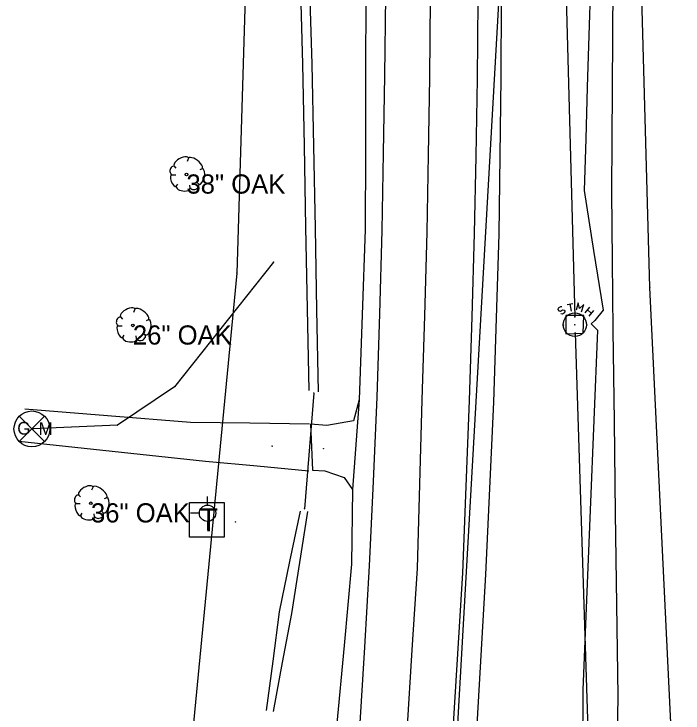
# Model space of a CAD drawing. Extents: x 1930288 to 1941089, y 588389 to 611475.
# Drawn here: x 1930813.6 to 1930987.9, y 598727.5 to 598909.6 of the extents above; entities that cross this region are included whole.
import ezdxf

# ---------------------------------------------------------------- set-up
doc = ezdxf.new("R2010")
doc.units = 0
for name, color, linetype in [('S_BASELINE', 7, 'Continuous'), ('S_DITCHLINE', 7, 'Continuous'), ('S_DRG_PT_SYM', 7, 'Continuous'), ('S_DRIVEWAY', 7, 'Continuous'), ('S_DROP_INLET', 7, 'Continuous'), ('S_EDGE_PAVEMENT', 7, 'Continuous'), ('S_GAS_UTILITIES', 7, 'Continuous'), ('S_MSC_PT_SYM', 7, 'Continuous'), ('S_PAVEMENT_CROWN', 7, 'Continuous'), ('S_SANITARY_SEWER', 7, 'Continuous'), ('S_SHOULDER', 7, 'Continuous'), ('S_SIDE_DRAIN', 7, 'Continuous'), ('S_STORM_SEWER', 7, 'Continuous'), ('S_TELEPHONE_UTILITIES', 7, 'Continuous'), ('S_TREE', 7, 'Continuous'), ('S_TREE_ANNOT', 7, 'Continuous'), ('S_UTILITY_POLE', 7, 'Continuous'), ('S_UTL_PT_SYM', 7, 'Continuous'), ('S_WATER_UTILITIES', 7, 'Continuous')]:
    doc.layers.add(name, color=color, linetype=linetype)

msp = doc.modelspace()

# ---------------------------------------------------------------- linework, layer by layer
at = {"layer": 'S_BASELINE'}
msp.add_line((1930894.27, 598110.49), (1930946.09, 599020.44), dxfattribs=at)
at = {"layer": 'S_DITCHLINE'}
for points in [[(1930885.69, 599030.55), (1930886.05, 599007.92), (1930886.41, 598985.29), (1930886.99, 598963.11), (1930887.58, 598940.93), (1930888.17, 598918.74), (1930888.75, 598896.56), (1930889.17, 598875.3), (1930889.58, 598854.04), (1930889.99, 598832.79), (1930890.41, 598811.53)], [(1930887.77, 599030.24), (1930888.22, 599008.14), (1930888.67, 598986.05), (1930889.3, 598963.68), (1930889.92, 598941.3), (1930890.55, 598918.93), (1930891.18, 598896.56), (1930891.61, 598875.21), (1930892.04, 598853.86), (1930892.46, 598832.51), (1930892.89, 598811.16)], [(1930958.74, 599016.33), (1930965.42, 599014.25), (1930966.89, 599005.44), (1930968.46, 598988.34), (1930970.03, 598971.25), (1930969.93, 598957.75), (1930969.84, 598944.26), (1930969.75, 598930.76), (1930969.66, 598917.27), (1930969.57, 598903.78), (1930969.47, 598890.28), (1930969.38, 598876.79), (1930969.29, 598863.29), (1930969.48, 598845.28), (1930969.68, 598827.26), (1930969.99, 598803.42), (1930970.29, 598779.58), (1930970.6, 598755.74), (1930970.91, 598731.9), (1930970.72, 598716.01)], [(1930958.59, 599014.73), (1930963.59, 599004.53), (1930964.52, 598987.9), (1930965.44, 598971.28), (1930965.04, 598957.82), (1930964.63, 598944.36), (1930964.22, 598930.9), (1930963.81, 598917.44), (1930963.41, 598903.98), (1930963, 598890.52), (1930962.59, 598877.06), (1930962.18, 598863.6), (1930964.65, 598848.03), (1930967.12, 598832.47), (1930964.95, 598829.79), (1930963.99, 598828.88), (1930965.68, 598827.27), (1930964.71, 598803.83), (1930963.74, 598780.39), (1930962.77, 598756.95), (1930961.8, 598733.51), (1930961.71, 598717.5)], [(1930888.13, 598780.09), (1930885.41, 598767), (1930882.7, 598753.91), (1930881.02, 598741.02), (1930879.34, 598728.13)], [(1930890.05, 598779.98), (1930887.96, 598766.7), (1930885.88, 598753.42), (1930883.52, 598740.66), (1930881.15, 598727.9)]]:
    msp.add_lwpolyline(points, dxfattribs=at)
at = {"layer": 'S_DRG_PT_SYM'}
for points in [[(1930891.72, 598810.87), (1930891.72, 598810.92), (1930891.72, 598810.87), (1930891.67, 598810.87), (1930891.72, 598810.87), (1930891.72, 598810.82), (1930891.72, 598810.87), (1930891.77, 598810.87)], [(1930889.32, 598780.73), (1930889.32, 598780.78), (1930889.32, 598780.73), (1930889.27, 598780.73), (1930889.32, 598780.73), (1930889.32, 598780.68), (1930889.32, 598780.73), (1930889.37, 598780.73)]]:
    msp.add_lwpolyline(points, dxfattribs=at)
at = {"layer": 'S_DRIVEWAY'}
for points in [[(1930903.51, 598809.06), (1930902.06, 598803.64), (1930895.14, 598802.42), (1930890.87, 598802.72), (1930891.4, 598790.75), (1930894.6, 598790.63), (1930899.62, 598788.9), (1930901.82, 598785.75)], [(1930890.56, 598802.74), (1930875.07, 598802.99), (1930859.57, 598803.23), (1930837.99, 598804.94), (1930816.4, 598806.66)], [(1930814.83, 598798.29), (1930839.15, 598795.7), (1930863.46, 598793.11), (1930876.95, 598791.87), (1930890.44, 598790.62)]]:
    msp.add_lwpolyline(points, dxfattribs=at)
at = {"layer": 'S_DROP_INLET'}
for points in [[(1930957.38, 598831.05), (1930957.37, 598826.27), (1930961.93, 598826.44), (1930962.11, 598831.03)], [(1930962.11, 598831.03), (1930957.38, 598831.05)]]:
    msp.add_lwpolyline(points, dxfattribs=at)
at = {"layer": 'S_EDGE_PAVEMENT'}
for points in [[(1930908.24, 599094.62), (1930908.7, 599076.29), (1930909.15, 599057.96), (1930909.61, 599039.62), (1930910.07, 599021.29), (1930910.34, 598999.36), (1930910.62, 598977.42), (1930910.62, 598956.27), (1930910.61, 598935.13), (1930910.4, 598914.36), (1930910.19, 598893.6), (1930909.84, 598873.38), (1930909.49, 598853.17), (1930908.82, 598831.47), (1930908.16, 598809.77), (1930907.16, 598787.82), (1930906.16, 598765.87), (1930904.92, 598744.7), (1930903.67, 598723.53)], [(1930932.32, 599092.44), (1930932.75, 599074.74), (1930933.17, 599057.04), (1930933.6, 599039.34), (1930934.02, 599021.64), (1930934.34, 598999.38), (1930934.66, 598977.12), (1930934.67, 598955.54), (1930934.68, 598933.95), (1930934.5, 598913.33), (1930934.31, 598892.71), (1930933.93, 598872.55), (1930933.55, 598852.4), (1930932.9, 598830.68), (1930932.25, 598808.95), (1930931.34, 598786.48), (1930930.43, 598764), (1930929.16, 598742.91), (1930927.89, 598721.82)]]:
    msp.add_lwpolyline(points, dxfattribs=at)
at = {"layer": 'S_GAS_UTILITIES'}
for p, q in [((1930881.2, 598844.97), (1930855.39, 598812.45)), ((1930855.39, 598812.45), (1930840.55, 598802.53)), ((1930814.96, 598798.2), (1930821.58, 598804.82)), ((1930814.96, 598804.82), (1930821.58, 598798.2)), ((1930840.55, 598802.53), (1930818.55, 598801.52))]:
    msp.add_line(p, q, dxfattribs=at)
msp.add_circle((1930818.27, 598801.51), 4.68, dxfattribs=at)
at = {"layer": 'S_MSC_PT_SYM'}
for points in [[(1930959.75, 598830.72), (1930959.75, 598830.77), (1930959.75, 598830.72), (1930959.7, 598830.72), (1930959.75, 598830.72), (1930959.75, 598830.67), (1930959.75, 598830.72), (1930959.8, 598830.72)], [(1930956.8, 598828.6), (1930956.8, 598828.65), (1930956.8, 598828.6), (1930956.75, 598828.6), (1930956.8, 598828.6), (1930956.8, 598828.55), (1930956.8, 598828.6), (1930956.85, 598828.6)], [(1930962.91, 598828.62), (1930962.91, 598828.67), (1930962.91, 598828.62), (1930962.86, 598828.62), (1930962.91, 598828.62), (1930962.91, 598828.57), (1930962.91, 598828.62), (1930962.96, 598828.62)], [(1930959.85, 598826.59), (1930959.85, 598826.64), (1930959.85, 598826.59), (1930959.8, 598826.59), (1930959.85, 598826.59), (1930959.85, 598826.54), (1930959.85, 598826.59), (1930959.9, 598826.59)], [(1930880.87, 598797.04), (1930880.87, 598797.09), (1930880.87, 598797.04), (1930880.82, 598797.04), (1930880.87, 598797.04), (1930880.87, 598796.99), (1930880.87, 598797.04), (1930880.92, 598797.04)], [(1930894.28, 598796.41), (1930894.28, 598796.46), (1930894.28, 598796.41), (1930894.23, 598796.41), (1930894.28, 598796.41), (1930894.28, 598796.35), (1930894.28, 598796.41), (1930894.33, 598796.41)]]:
    msp.add_lwpolyline(points, dxfattribs=at)
at = {"layer": 'S_PAVEMENT_CROWN'}
msp.add_lwpolyline([(1930919.68, 599093.9), (1930920.14, 599075.83), (1930920.59, 599057.77), (1930921.04, 599039.71), (1930921.49, 599021.64), (1930921.81, 598999.22), (1930922.13, 598976.81), (1930922.17, 598955.6), (1930922.2, 598934.39), (1930922.05, 598913.69), (1930921.9, 598892.99), (1930921.54, 598872.9), (1930921.18, 598852.8), (1930920.54, 598830.95), (1930919.9, 598809.1), (1930919.28, 598787.14), (1930918.67, 598765.18), (1930917.3, 598743.97), (1930915.93, 598722.77)], dxfattribs=at)
at = {"layer": 'S_SANITARY_SEWER'}
for p, q in [((1930979.26, 598838.38), (1930967.81, 599265.02)), ((1930987.94, 598658.53), (1930979.26, 598838.38))]:
    msp.add_line(p, q, dxfattribs=at)
at = {"layer": 'S_SHOULDER'}
for points in [[(1930937.38, 599115.75), (1930938.49, 599091.15), (1930939.12, 599068.01), (1930939.38, 599055.8), (1930939.72, 599039.21), (1930940.06, 599022.62), (1930940.02, 598999.95), (1930939.99, 598977.27), (1930940.29, 598955.61), (1930940.58, 598933.95), (1930940.54, 598913.5), (1930940.49, 598893.05), (1930940.2, 598872.63), (1930939.9, 598852.22), (1930939.23, 598830.34), (1930938.55, 598808.45), (1930937.5, 598786.02), (1930936.44, 598763.59), (1930935.25, 598742.5), (1930934.05, 598721.41)], [(1930901.66, 599094.84), (1930902.24, 599076.43), (1930902.81, 599058.02), (1930903.38, 599039.62), (1930903.95, 599021.21), (1930904.32, 598999.45), (1930904.69, 598977.7), (1930904.98, 598956.64), (1930905.27, 598935.59), (1930905.24, 598914.82), (1930905.22, 598894.05), (1930905.16, 598873.77), (1930905.09, 598853.48), (1930904.3, 598831.27), (1930903.51, 598809.06), (1930901.82, 598785.75), (1930901.57, 598766.31), (1930899.62, 598745.09), (1930897.67, 598723.87)]]:
    msp.add_lwpolyline(points, dxfattribs=at)
at = {"layer": 'S_SIDE_DRAIN'}
msp.add_line((1930891.72, 598810.87), (1930889.32, 598780.73), dxfattribs=at)
at = {"layer": 'S_STORM_SEWER'}
for p, q in [((1930954.8, 599013.58), (1930959.75, 598830.72)), ((1930955.97, 598833.36), (1930955.42, 598832.98)), ((1930956.39, 598833.29), (1930955.97, 598833.36)), ((1930957.71, 598833.95), (1930959.22, 598834.22)), ((1930958.48, 598834.1), (1930958.83, 598832.16)), ((1930962.4, 598831.74), (1930963.64, 598833.21)), ((1930955.42, 598832.98), (1930955.35, 598832.59)), ((1930955.35, 598832.59), (1930955.54, 598832.32)), ((1930955.54, 598832.32), (1930955.97, 598832.2)), ((1930955.97, 598832.2), (1930956.51, 598832.55)), ((1930956.51, 598831.39), (1930956.12, 598831.47)), ((1930956.51, 598832.55), (1930956.97, 598832.47)), ((1930957.05, 598831.78), (1930956.51, 598831.39)), ((1930956.97, 598832.47), (1930957.13, 598832.2)), ((1930957.13, 598832.2), (1930957.05, 598831.78)), ((1930963.06, 598832.51), (1930964.03, 598831.7)), ((1930964.61, 598832.4), (1930963.37, 598830.92)), ((1930959.85, 598826.59), (1930965.03, 598662.59))]:
    msp.add_line(p, q, dxfattribs=at)
msp.add_lwpolyline([(1930961.51, 598832.05), (1930962.05, 598833.91), (1930961, 598832.9), (1930960.62, 598834.33), (1930960.07, 598832.47)], dxfattribs=at)
msp.add_circle((1930959.75, 598828.67), 3.05, dxfattribs=at)
at = {"layer": 'S_TELEPHONE_UTILITIES'}
msp.add_lwpolyline([(1930859.33, 598773.36), (1930859.33, 598782.36), (1930868.33, 598782.36), (1930868.33, 598773.36)], close=True, dxfattribs=at)
at = {"layer": 'S_TREE'}
for p, q in [((1930859.08, 598872.07), (1930858.7, 598871.22)), ((1930855.29, 598870.06), (1930855.79, 598869.47)), ((1930854.63, 598867.73), (1930855.75, 598867.73)), ((1930862.65, 598869.28), (1930861.99, 598869.01)), ((1930855.79, 598864.55), (1930856.26, 598865.25)), ((1930859.47, 598864.28), (1930859.39, 598865.06)), ((1930861.87, 598865.17), (1930861.41, 598865.6)), ((1930845.12, 598832.74), (1930844.74, 598831.89)), ((1930841.33, 598830.73), (1930841.83, 598830.14)), ((1930848.69, 598829.95), (1930848.03, 598829.68)), ((1930840.67, 598828.4), (1930841.79, 598828.4)), ((1930841.83, 598825.22), (1930842.29, 598825.92)), ((1930847.91, 598825.84), (1930847.45, 598826.27)), ((1930845.51, 598824.95), (1930845.43, 598825.73)), ((1930834.2, 598786.39), (1930833.81, 598785.54)), ((1930830.4, 598784.38), (1930830.91, 598783.8)), ((1930837.77, 598783.6), (1930837.11, 598783.33)), ((1930829.74, 598782.05), (1930830.87, 598782.05)), ((1930830.91, 598778.88), (1930831.37, 598779.57)), ((1930834.59, 598778.6), (1930834.51, 598779.38)), ((1930836.99, 598779.5), (1930836.53, 598779.92))]:
    msp.add_line(p, q, dxfattribs=at)
for centre in [(1930858.53, 598867.82), (1930844.57, 598828.49), (1930833.64, 598782.15)]:
    msp.add_circle(centre, 0.341, dxfattribs=at)
for centre, major_axis, ratio, start_param, end_param in [((1930857.19, 598871.03), (1.86, 1.08), 0.471018, 0, 3.141593), ((1930860.85, 598870.7), (-1.81, 1.36), 0.405113, 3.141593, 6.283186), ((1930854.96, 598868.91), (0.31, 1.03), 0.646762, 0, 3.141593), ((1930855.26, 598866.26), (-0.61, 1.6), 0.420543, 6.283185, 9.424777), ((1930862.2, 598867.29), (0.46, 2.04), 0.482994, 3.141593, 6.283185), ((1930857.72, 598864.48), (-1.83, 0.19), 0.529943, 0, 3.141593), ((1930860.68, 598864.77), (1.09, 0.46), 0.711534, 3.141592, 6.283185), ((1930843.23, 598831.7), (1.86, 1.08), 0.471018, 0, 3.141593), ((1930846.88, 598831.37), (-1.81, 1.36), 0.405113, 3.141593, 6.283186), ((1930840.99, 598829.58), (0.31, 1.03), 0.646762, 0, 3.141593), ((1930848.24, 598827.96), (0.46, 2.04), 0.482994, 3.141593, 6.283185), ((1930841.3, 598826.93), (-0.61, 1.6), 0.420543, 6.283185, 9.424777), ((1930846.72, 598825.44), (1.09, 0.46), 0.711534, 3.141592, 6.283185), ((1930843.76, 598825.15), (-1.83, 0.19), 0.529943, 0, 3.141593), ((1930832.31, 598785.35), (1.86, 1.08), 0.471018, 0, 3.141593), ((1930835.96, 598785.03), (-1.81, 1.36), 0.405113, 3.141593, 6.283186), ((1930830.07, 598783.23), (0.31, 1.03), 0.646762, 0, 3.141593), ((1930830.38, 598780.58), (-0.61, 1.6), 0.420543, 6.283185, 9.424777), ((1930837.32, 598781.62), (0.46, 2.04), 0.482994, 3.141593, 6.283185), ((1930832.84, 598778.8), (-1.83, 0.19), 0.529943, 0, 3.141593), ((1930835.79, 598779.1), (1.09, 0.46), 0.711534, 3.141592, 6.283185)]:
    msp.add_ellipse(centre, major_axis=major_axis, ratio=ratio, start_param=start_param, end_param=end_param, dxfattribs=at)
at = {"layer": 'S_UTILITY_POLE'}
for p, q in [((1930864.02, 598781.67), (1930864.02, 598783.91)), ((1930861.93, 598779.53), (1930859.61, 598779.53)), ((1930864.1, 598775.12), (1930864.1, 598777.44))]:
    msp.add_line(p, q, dxfattribs=at)
msp.add_circle((1930864.03, 598779.56), 2.13, dxfattribs=at)
at = {"layer": 'S_UTL_PT_SYM'}
for points in [[(1930881.2, 598844.97), (1930881.2, 598845.02), (1930881.2, 598844.97), (1930881.15, 598844.97), (1930881.2, 598844.97), (1930881.2, 598844.92), (1930881.2, 598844.97), (1930881.25, 598844.97)], [(1930871.67, 598842.11), (1930871.67, 598842.16), (1930871.67, 598842.11), (1930871.62, 598842.11), (1930871.67, 598842.11), (1930871.67, 598842.06), (1930871.67, 598842.11), (1930871.72, 598842.11)], [(1930979.26, 598838.38), (1930979.26, 598838.43), (1930979.26, 598838.38), (1930979.21, 598838.38), (1930979.26, 598838.38), (1930979.26, 598838.33), (1930979.26, 598838.38), (1930979.31, 598838.38)], [(1930959.75, 598830.72), (1930959.75, 598830.77), (1930959.75, 598830.72), (1930959.7, 598830.72), (1930959.75, 598830.72), (1930959.75, 598830.67), (1930959.75, 598830.72), (1930959.8, 598830.72)], [(1930959.75, 598828.67), (1930959.75, 598828.72), (1930959.75, 598828.67), (1930959.7, 598828.67), (1930959.75, 598828.67), (1930959.75, 598828.62), (1930959.75, 598828.67), (1930959.8, 598828.67)], [(1930959.85, 598826.59), (1930959.85, 598826.64), (1930959.85, 598826.59), (1930959.8, 598826.59), (1930959.85, 598826.59), (1930959.85, 598826.54), (1930959.85, 598826.59), (1930959.9, 598826.59)], [(1930855.39, 598812.45), (1930855.39, 598812.5), (1930855.39, 598812.45), (1930855.34, 598812.45), (1930855.39, 598812.45), (1930855.39, 598812.4), (1930855.39, 598812.45), (1930855.44, 598812.45)], [(1930840.55, 598802.53), (1930840.55, 598802.58), (1930840.55, 598802.53), (1930840.5, 598802.53), (1930840.55, 598802.53), (1930840.55, 598802.48), (1930840.55, 598802.53), (1930840.6, 598802.53)], [(1930818.55, 598801.52), (1930818.55, 598801.57), (1930818.55, 598801.52), (1930818.5, 598801.52), (1930818.55, 598801.52), (1930818.55, 598801.47), (1930818.55, 598801.52), (1930818.6, 598801.52)], [(1930871.3, 598777.28), (1930871.3, 598777.33), (1930871.3, 598777.28), (1930871.25, 598777.28), (1930871.3, 598777.28), (1930871.3, 598777.23), (1930871.3, 598777.28), (1930871.35, 598777.28)]]:
    msp.add_lwpolyline(points, dxfattribs=at)
at = {"layer": 'S_WATER_UTILITIES'}
for p, q in [((1930877.25, 599023.82), (1930871.67, 598842.11)), ((1930871.67, 598842.11), (1930854.29, 598662.35))]:
    msp.add_line(p, q, dxfattribs=at)

# ---------------------------------------------------------------- texts
at = {"layer": 'S_GAS_UTILITIES'}
for s, p in [('G', (1930814.45, 598800.04)), ('M', (1930820.02, 598799.94))]:
    msp.add_text(s, height=3.3, rotation=360, dxfattribs=at).set_placement(p)
at = {"layer": 'S_TELEPHONE_UTILITIES'}
msp.add_text('T', height=6, rotation=360, dxfattribs=at).set_placement((1930861.89, 598774.86))
at = {"layer": 'S_TREE_ANNOT'}
for s, p in [('38" OAK', (1930858.53, 598862.82)), ('26" OAK', (1930844.57, 598823.49)), ('36" OAK', (1930833.64, 598777.15))]:
    msp.add_text(s, height=5, dxfattribs=at).set_placement(p)

doc.saveas('drawing.dxf')
